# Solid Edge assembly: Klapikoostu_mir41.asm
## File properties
Author: Türk
Template: Iso Assembly.asm
Last saved by: Türk
Revision: 3
Application: Solid Edge
Username: Türk
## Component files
Klapipuks.par
Klapi vedru_mir1.par
Klapp.par
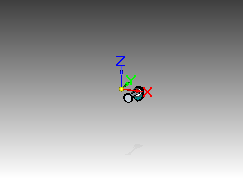
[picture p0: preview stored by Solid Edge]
